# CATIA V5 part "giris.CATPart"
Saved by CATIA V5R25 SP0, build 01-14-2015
Part number: giris
Bounding box of the stored display mesh (mm): x 0 to 10, y -12.486 to 87.486, z -12.5 to 12.5
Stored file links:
  C:\Users\Aidata\Downloads\giris.CATPart
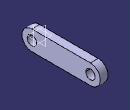
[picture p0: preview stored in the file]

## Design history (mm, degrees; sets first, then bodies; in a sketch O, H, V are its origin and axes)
Body1 (main body)
  Sketch1 on yz-plane, origin (0, 0, 0), H (0, 1, 0), V (0, 0, 1)
    construction line L1 (0, 0) -> (75, 0)
    line L2 (0, 12.5) -> (75, 12.5)
    line L3 (75, -12.5) -> (0, -12.5)
    arc A1 centre (75, 0) radius 12.5 from (75, 12.5) to (75, -12.5) cw
    arc A2 centre (0, 0) radius 12.5 from (0, -12.5) to (0, 12.5) cw
    circle A3 centre (0, 0) radius 6
    circle A4 centre (75, 0) radius 6
    distance L3 L2 = 25
    radius A3 = 6
    radius A4 = 6
    distance A1 A2 = 100
    horizontal: L1 H
    tangency: A1 L2, A2 L2, A1 L3, A2 L3
  Pad1: profile Sketch1, direction (1, 0, 0), length 10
